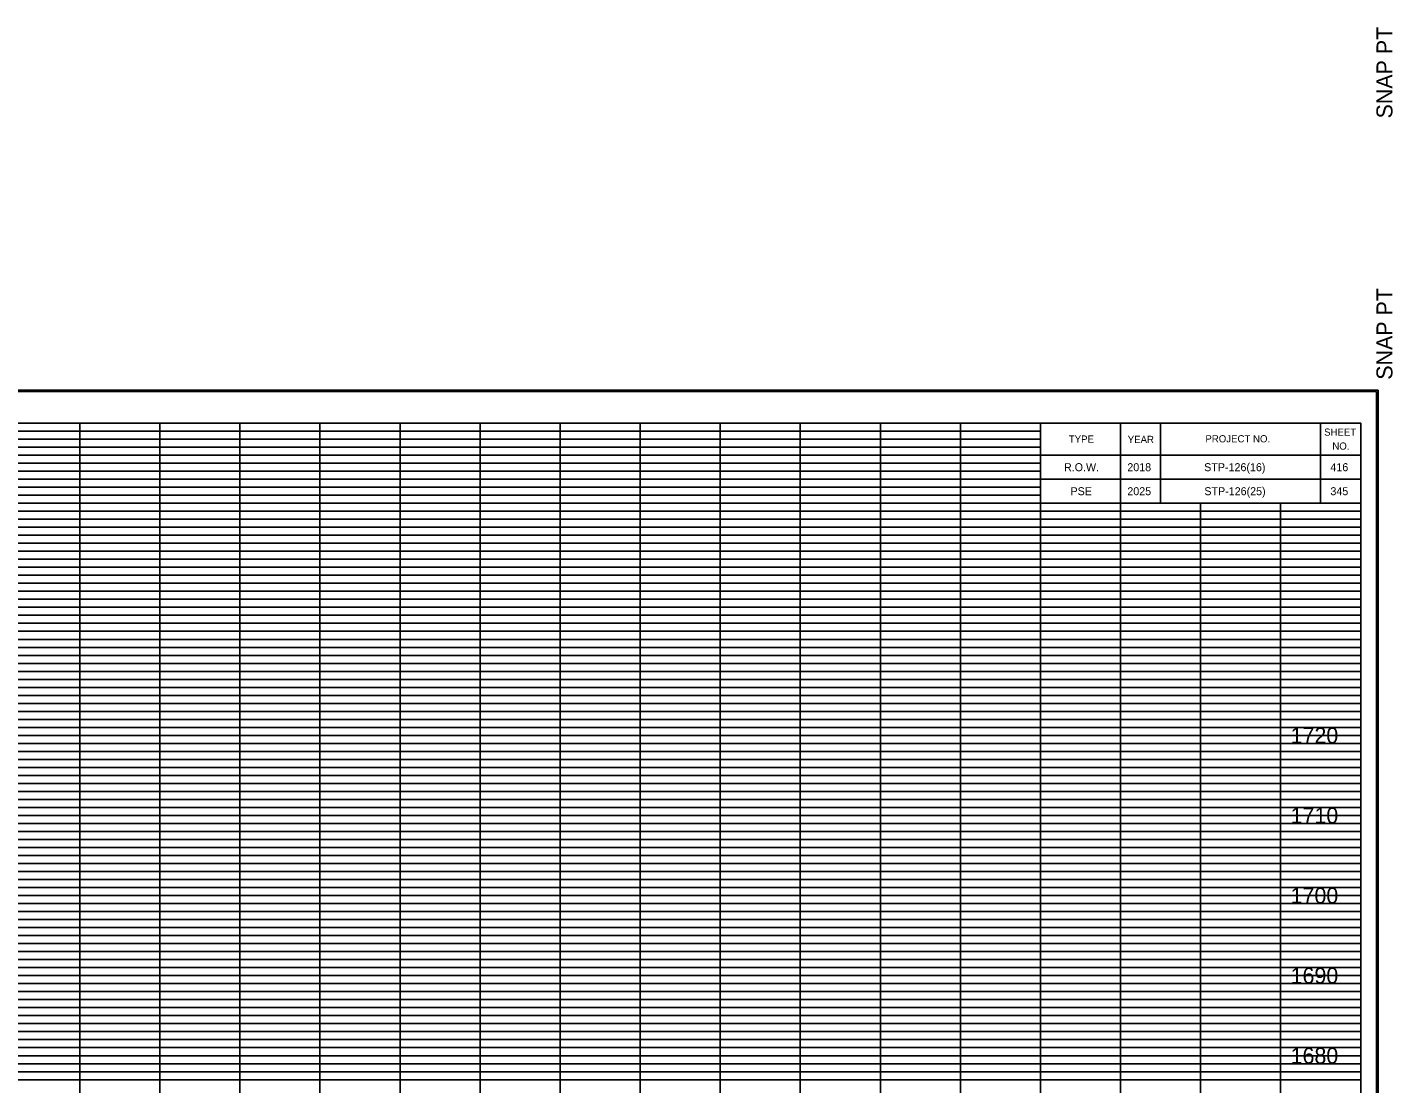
# Model space of a CAD drawing. Extents: x 980 to 2228, y 978 to 2394.
# Drawn here: x 1153.4 to 1324, y 1397.5 to 1529.4 of the extents above; entities that cross this region are included whole.
import ezdxf

# ---------------------------------------------------------------- set-up
doc = ezdxf.new("R2010")
doc.units = 0
for name, color, linetype in [('DESIGN - SCRATCH - User 1', 7, 'Continuous'), ('DESIGN - SHEET - Corner Text', 7, 'Continuous'), ('DESIGN - SHEET - Light Grid', 7, 'Continuous'), ('DESIGN - SHEET - Linework', 7, 'Continuous'), ('DESIGN - SHEET - Plot Shape', 7, 'Continuous'), ('DESIGN - TYPICAL - Finished Grade and Subgrade', 7, 'Continuous')]:
    doc.layers.add(name, color=color, linetype=linetype)

# ---------------------------------------------------------------- blocks, each defined once
blk = doc.blocks.new('XSTSHT')
at = {"layer": 'DESIGN - SCRATCH - User 1'}
for p, q in [((28.5, 20.45), (28.5, 20.45)), ((29.24, 20.45), (29.24, 20.45)), ((30.49, 20.45), (30.49, 20.45)), ((31.74, 20.45), (31.74, 20.45)), ((28.5, 20.15), (28.5, 20.15)), ((29.24, 20.15), (29.24, 20.15)), ((30.49, 20.15), (30.49, 20.15)), ((31.74, 20.15), (31.74, 20.15))]:
    blk.add_line(p, q, dxfattribs=at)
at = {"layer": 'DESIGN - SHEET - Light Grid'}
for p, q in [((8, 20.9), (16, 20.9)), ((16, 20.9), (24, 20.9)), ((24, 20.9), (28, 20.9)), ((8, 20.8), (16, 20.8)), ((8, 20.7), (16, 20.7)), ((16, 20.8), (24, 20.8)), ((16, 20.7), (24, 20.7)), ((24, 20.8), (28, 20.8)), ((24, 20.7), (28, 20.7)), ((8, 20.6), (16, 20.6)), ((8, 20.5), (16, 20.5)), ((16, 20.6), (24, 20.6)), ((16, 20.5), (24, 20.5)), ((24, 20.6), (28, 20.6)), ((24, 20.5), (28, 20.5)), ((8, 20.4), (16, 20.4)), ((8, 20.3), (16, 20.3)), ((16, 20.4), (24, 20.4)), ((16, 20.3), (24, 20.3)), ((24, 20.4), (28, 20.4)), ((24, 20.3), (28, 20.3)), ((8, 20.2), (16, 20.2)), ((16, 20.2), (24, 20.2)), ((24, 20.2), (28, 20.2)), ((8, 20.1), (16, 20.1)), ((16, 20.1), (24, 20.1)), ((24, 20.1), (28, 20.1)), ((8, 19.9), (16, 19.9)), ((8, 19.8), (16, 19.8)), ((16, 19.9), (24, 19.9)), ((16, 19.8), (24, 19.8)), ((24, 19.9), (32, 19.9)), ((24, 19.8), (32, 19.8)), ((8, 19.7), (16, 19.7)), ((16, 19.7), (24, 19.7)), ((24, 19.7), (32, 19.7)), ((8, 19.6), (16, 19.6)), ((8, 19.5), (16, 19.5)), ((16, 19.6), (24, 19.6)), ((16, 19.5), (24, 19.5)), ((24, 19.6), (32, 19.6)), ((24, 19.5), (32, 19.5)), ((8, 19.4), (16, 19.4)), ((8, 19.3), (16, 19.3)), ((16, 19.4), (24, 19.4)), ((16, 19.3), (24, 19.3)), ((24, 19.4), (32, 19.4)), ((24, 19.3), (32, 19.3)), ((8, 19.2), (16, 19.2)), ((16, 19.2), (24, 19.2)), ((24, 19.2), (32, 19.2)), ((8, 19.1), (16, 19.1)), ((16, 19.1), (24, 19.1)), ((24, 19.1), (32, 19.1)), ((8, 18.9), (16, 18.9)), ((8, 18.8), (16, 18.8)), ((16, 18.9), (24, 18.9)), ((16, 18.8), (24, 18.8)), ((24, 18.9), (32, 18.9)), ((24, 18.8), (32, 18.8)), ((8, 18.7), (16, 18.7)), ((8, 18.6), (16, 18.6)), ((16, 18.7), (24, 18.7)), ((16, 18.6), (24, 18.6)), ((24, 18.7), (32, 18.7)), ((24, 18.6), (32, 18.6)), ((8, 18.5), (16, 18.5)), ((16, 18.5), (24, 18.5)), ((24, 18.5), (32, 18.5)), ((8, 18.4), (16, 18.4)), ((8, 18.3), (16, 18.3)), ((16, 18.4), (24, 18.4)), ((16, 18.3), (24, 18.3)), ((24, 18.4), (32, 18.4)), ((24, 18.3), (32, 18.3)), ((8, 18.2), (16, 18.2)), ((8, 18.1), (16, 18.1)), ((16, 18.2), (24, 18.2)), ((16, 18.1), (24, 18.1)), ((24, 18.2), (32, 18.2)), ((24, 18.1), (32, 18.1)), ((8, 17.9), (16, 17.9)), ((8, 17.8), (16, 17.8)), ((16, 17.9), (24, 17.9)), ((16, 17.8), (24, 17.8)), ((24, 17.9), (32, 17.9)), ((24, 17.8), (32, 17.8)), ((8, 17.7), (16, 17.7)), ((8, 17.6), (16, 17.6)), ((16, 17.7), (24, 17.7)), ((16, 17.6), (24, 17.6)), ((24, 17.7), (32, 17.7)), ((24, 17.6), (32, 17.6)), ((8, 17.5), (16, 17.5)), ((8, 17.4), (16, 17.4)), ((16, 17.5), (24, 17.5)), ((16, 17.4), (24, 17.4)), ((24, 17.5), (32, 17.5)), ((24, 17.4), (32, 17.4)), ((8, 17.3), (16, 17.3)), ((16, 17.3), (24, 17.3)), ((24, 17.3), (32, 17.3)), ((8, 17.2), (16, 17.2)), ((8, 17.1), (16, 17.1)), ((16, 17.2), (24, 17.2)), ((16, 17.1), (24, 17.1)), ((24, 17.2), (32, 17.2)), ((24, 17.1), (32, 17.1)), ((8, 16.9), (16, 16.9)), ((16, 16.9), (24, 16.9)), ((24, 16.9), (32, 16.9)), ((8, 16.8), (16, 16.8)), ((16, 16.8), (24, 16.8)), ((24, 16.8), (32, 16.8)), ((8, 16.7), (16, 16.7)), ((8, 16.6), (16, 16.6)), ((16, 16.7), (24, 16.7)), ((16, 16.6), (24, 16.6)), ((24, 16.7), (32, 16.7)), ((24, 16.6), (32, 16.6)), ((8, 16.5), (16, 16.5)), ((8, 16.4), (16, 16.4)), ((16, 16.5), (24, 16.5)), ((16, 16.4), (24, 16.4)), ((24, 16.5), (32, 16.5)), ((24, 16.4), (32, 16.4)), ((8, 16.3), (16, 16.3)), ((16, 16.3), (24, 16.3)), ((24, 16.3), (32, 16.3)), ((8, 16.2), (16, 16.2)), ((8, 16.1), (16, 16.1)), ((16, 16.2), (24, 16.2)), ((16, 16.1), (24, 16.1)), ((24, 16.2), (32, 16.2)), ((24, 16.1), (32, 16.1)), ((8, 15.9), (16, 15.9)), ((16, 15.9), (24, 15.9)), ((24, 15.9), (32, 15.9)), ((8, 15.8), (16, 15.8)), ((8, 15.7), (16, 15.7)), ((16, 15.8), (24, 15.8)), ((16, 15.7), (24, 15.7)), ((24, 15.8), (32, 15.8)), ((24, 15.7), (32, 15.7)), ((8, 15.6), (16, 15.6)), ((16, 15.6), (24, 15.6)), ((24, 15.6), (32, 15.6)), ((8, 15.5), (16, 15.5)), ((8, 15.4), (16, 15.4)), ((16, 15.5), (24, 15.5)), ((16, 15.4), (24, 15.4)), ((24, 15.5), (32, 15.5)), ((24, 15.4), (32, 15.4)), ((8, 15.3), (16, 15.3)), ((8, 15.2), (16, 15.2)), ((16, 15.3), (24, 15.3)), ((16, 15.2), (24, 15.2)), ((24, 15.3), (32, 15.3)), ((24, 15.2), (32, 15.2)), ((8, 15.1), (16, 15.1)), ((16, 15.1), (24, 15.1)), ((24, 15.1), (32, 15.1)), ((8, 14.9), (16, 14.9)), ((16, 14.9), (24, 14.9)), ((24, 14.9), (32, 14.9)), ((8, 14.8), (16, 14.8)), ((8, 14.7), (16, 14.7)), ((16, 14.8), (24, 14.8)), ((16, 14.7), (24, 14.7)), ((24, 14.8), (32, 14.8)), ((24, 14.7), (32, 14.7)), ((8, 14.6), (16, 14.6)), ((8, 14.5), (16, 14.5)), ((16, 14.6), (24, 14.6)), ((16, 14.5), (24, 14.5)), ((24, 14.6), (32, 14.6)), ((24, 14.5), (32, 14.5)), ((8, 14.4), (16, 14.4)), ((16, 14.4), (24, 14.4)), ((24, 14.4), (32, 14.4)), ((8, 14.3), (16, 14.3)), ((8, 14.2), (16, 14.2)), ((16, 14.3), (24, 14.3)), ((16, 14.2), (24, 14.2)), ((24, 14.3), (32, 14.3)), ((24, 14.2), (32, 14.2)), ((8, 14.1), (16, 14.1)), ((16, 14.1), (24, 14.1)), ((24, 14.1), (32, 14.1)), ((8, 13.9), (16, 13.9)), ((16, 13.9), (24, 13.9)), ((24, 13.9), (32, 13.9)), ((8, 13.8), (16, 13.8)), ((8, 13.7), (16, 13.7)), ((16, 13.8), (24, 13.8)), ((16, 13.7), (24, 13.7)), ((24, 13.8), (32, 13.8)), ((24, 13.7), (32, 13.7)), ((8, 13.6), (16, 13.6)), ((8, 13.5), (16, 13.5)), ((16, 13.6), (24, 13.6)), ((16, 13.5), (24, 13.5)), ((24, 13.6), (32, 13.6)), ((24, 13.5), (32, 13.5)), ((8, 13.4), (16, 13.4)), ((16, 13.4), (24, 13.4)), ((24, 13.4), (32, 13.4)), ((8, 13.3), (16, 13.3)), ((8, 13.2), (16, 13.2)), ((16, 13.3), (24, 13.3)), ((16, 13.2), (24, 13.2)), ((24, 13.3), (32, 13.3)), ((24, 13.2), (32, 13.2)), ((8, 13.1), (16, 13.1)), ((16, 13.1), (24, 13.1)), ((24, 13.1), (32, 13.1)), ((8, 12.9), (16, 12.9)), ((8, 12.8), (16, 12.8)), ((16, 12.9), (24, 12.9)), ((16, 12.8), (24, 12.8)), ((24, 12.9), (32, 12.9)), ((24, 12.8), (32, 12.8))]:
    blk.add_line(p, q, dxfattribs=at)
at = {"layer": 'DESIGN - SHEET - Linework'}
for p, q in [((-1.823, 21.414), (32.217, 21.414)), ((32.217, 21.414), (32.217, -0.414)), ((16, 0), (16, 21)), ((17, 0), (17, 21)), ((18, 0), (18, 21)), ((19, 0), (19, 21)), ((20, 0), (20, 21)), ((21, 0), (21, 21)), ((22, 0), (22, 21)), ((23, 0), (23, 21)), ((24, 0), (24, 21)), ((25, 0), (25, 21)), ((26, 0), (26, 21)), ((27, 0), (27, 21)), ((0, 20), (28, 20)), ((28, 0), (28, 20)), ((29, 0), (29, 20)), ((30, 0), (30, 20)), ((31, 0), (31, 20)), ((0, 19), (32, 19)), ((0, 18), (32, 18)), ((0, 17), (32, 17)), ((0, 16), (32, 16)), ((0, 15), (32, 15)), ((0, 14), (32, 14)), ((0, 13), (32, 13))]:
    blk.add_line(p, q, dxfattribs=at)
for points in [[(0, 21), (0, 0), (32, 0), (32, 21), (0, 21)], [(28, 21), (28, 20), (32, 20), (32, 21), (31.5, 21), (31.5, 20), (29.5, 20), (29.5, 21), (29, 21), (29, 20), (32, 20), (28, 20), (28, 20.3), (32, 20.3), (32, 20.6), (28, 20.6)]]:
    blk.add_lwpolyline(points, dxfattribs=at)
at = {"layer": 'DESIGN - SHEET - Plot Shape'}
for points in [[(-1.803, 21.394), (32.197, 21.394), (32.197, -0.394), (-1.803, -0.394)], [(-0.85, 21), (32, 21), (32, -0.25), (-0.85, -0.25)]]:
    blk.add_lwpolyline(points, close=True, dxfattribs=at)
at = {"layer": 'DESIGN - SHEET - Corner Text'}
for s, p in [('  SNAP PT', (32.397, 21.394)), ('SNAP PT  ', (32.397, -2.194))]:
    blk.add_text(s, height=0.2, rotation=90, dxfattribs=at).set_placement(p)
for s, p in [('TYPE', (28.354, 20.756)), ('YEAR', (29.09, 20.752)), ('PROJECT NO.', (30.06, 20.76)), ('SHEET', (31.543, 20.843)), ('NO.', (31.646, 20.669))]:
    blk.add_text(s, height=0.09, dxfattribs=at).set_placement(p)

msp = doc.modelspace()

# ---------------------------------------------------------------- linework, layer by layer
at = {"layer": 'DESIGN - SHEET - Plot Shape'}
msp.add_lwpolyline([(991.5, 1480), (1320, 1480), (1320, 1267.5), (991.5, 1267.5)], close=True, dxfattribs=at)

# ---------------------------------------------------------------- block references
at = {"layer": 'DESIGN - TYPICAL - Finished Grade and Subgrade', "xscale": 10, "yscale": 10}
for p in [(1000, 1540), (1000, 1270)]:
    msp.add_blockref('XSTSHT', p, dxfattribs=at)

# ---------------------------------------------------------------- texts
at = {"layer": 'DESIGN - SHEET - Corner Text'}
for s, height, p in [('R.O.W.', 1, (1282.94, 1474)), ('2018', 1, (1290.85, 1474)), ('STP-126(16)', 1, (1300.45, 1474)), ('416', 1, (1316.22, 1474)), ('PSE', 1, (1283.75, 1471)), ('2025', 1, (1290.85, 1471)), ('STP-126(25)', 1, (1300.47, 1471)), ('345', 1, (1316.22, 1471)), ('1720', 2, (1311.25, 1440)), ('1710', 2, (1311.25, 1430)), ('1700', 2, (1311.25, 1420)), ('1690', 2, (1311.25, 1410)), ('1680', 2, (1311.25, 1400))]:
    msp.add_text(s, height=height, dxfattribs=at).set_placement(p)

doc.saveas('drawing.dxf')
